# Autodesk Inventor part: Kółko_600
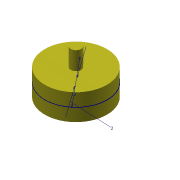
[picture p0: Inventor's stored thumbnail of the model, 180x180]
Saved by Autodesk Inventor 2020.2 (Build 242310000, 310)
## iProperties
Created: 2014-12
Part Number: Kółko_600
Material: Ogólny
Document SubType Name: Modeling
Designer: F.Stasiak
Mass: 0.587478 g
Surface Area: 4.58673 cm^2
Volume: 0.587478 cm^3
Density: 1 g/cm^3
Appearance: Kanarkowa
Catalog Web Link: www.expertbooks.pl
Manager: www.cadconsulting.pl
Company: Fabian Stasiak CAD Consulting
Author: F.Stasiak
Subject: Zbiór ćwiczeń. Autodesk Inventor 2020. Kurs Professional
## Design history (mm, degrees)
sketch "Szkic1"
  geometry: C1 r 1 at (0, 0); C2 r 6 at (0, 0); 1 further point
  constraints: 2 centre point, 2 coincident
  dimensions: "d0" = 2 diameter of C1; "d1" = 12 diameter of C2
extrude "Wyciągnięcie proste1" new body sketch "Szkic1" stored distance "d2" = 5; taper "d3" = 0 deg
extrude "Wyciągnięcie proste2" join sketch "Szkic1" stored distance "d4" = 12; taper "d5" = 0 deg
node "Bryła1"
